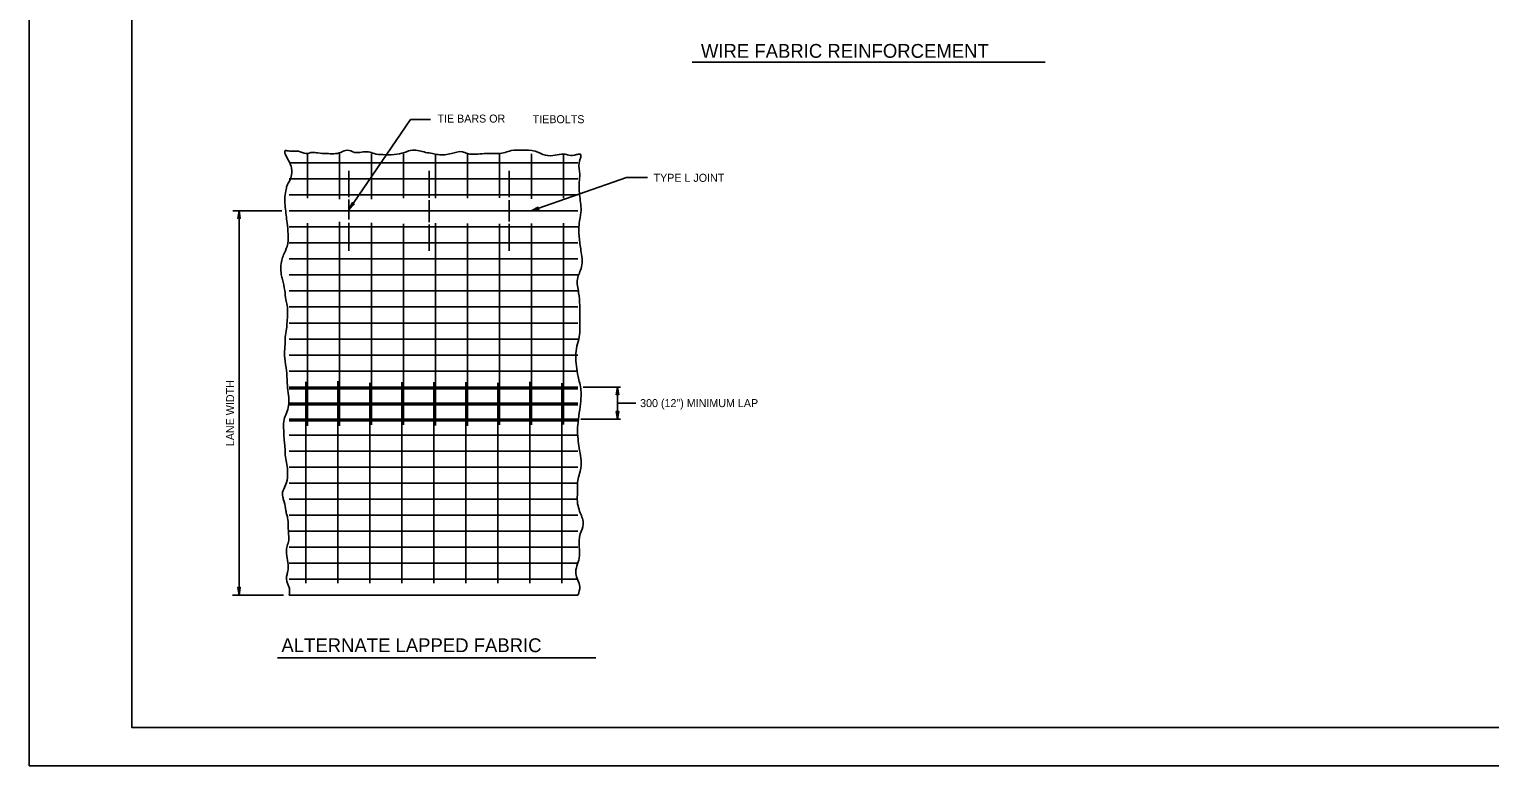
# Model space of a CAD drawing. Extents: x 638703 to 639608, y 298343 to 298937.
# Drawn here: x 638703 to 639273, y 298343 to 298630 of the extents above; entities that cross this region are included whole.
import ezdxf

# ---------------------------------------------------------------- set-up
doc = ezdxf.new("R2010")
doc.units = 0
for name, color, linetype in [('1', 7, 'Continuous'), ('2', 7, 'Continuous'), ('3', 7, 'Continuous'), ('PLT-BNDY', 7, 'Continuous')]:
    doc.layers.add(name, color=color, linetype=linetype)

msp = doc.modelspace()

# ---------------------------------------------------------------- linework, layer by layer
at = {"layer": '1'}
msp.add_lwpolyline([(639528.936, 298357.638375), (639528.936, 298921.638375), (638742.936, 298921.638375), (638742.936, 298357.638375), (639528.936, 298357.638375), (639528.936, 298383.997375), (639328.936, 298383.997375), (639328.936, 298448.674875), (639528.936, 298448.674875), (639528.936, 298477.638375), (639328.936, 298477.638375), (639328.936, 298357.638375), (639407.7375, 298357.638375), (639407.7375, 298383.997375), (639407.7375, 298357.638375), (639484.7375, 298357.638375), (639484.7375, 298383.997375), (639484.7375, 298371.680875), (639528.936, 298371.680875)], dxfattribs=at)
at = {"layer": '2'}
for p, q in [((638961.78875, 298617.283625), (639099.593, 298617.283625)), ((638851.82375, 298594.872625), (638827.7715, 298559.651875)), ((638859.66125, 298594.872625), (638851.82375, 298594.872625)), ((638917.184, 298577.958125), (638804.41525, 298577.958125)), ((638811.557, 298581.493625), (638811.557, 298564.235125)), ((638824.057, 298581.493625), (638824.057, 298563.858125)), ((638836.557, 298581.493625), (638836.557, 298563.778875)), ((638849.057, 298581.493625), (638849.057, 298564.235125)), ((638861.557, 298581.493625), (638861.557, 298564.235125)), ((638874.057, 298581.493625), (638874.057, 298564.135125)), ((638886.557, 298581.493625), (638886.557, 298564.314375)), ((638899.057, 298581.493625), (638899.057, 298563.937375)), ((638911.557, 298581.493625), (638911.557, 298564.214375)), ((638827.7715, 298574.833125), (638827.7715, 298564.543625)), ((638859.0215, 298574.833125), (638859.0215, 298564.266375)), ((638890.2715, 298574.833125), (638890.2715, 298564.543625)), ((638917.184, 298571.708125), (638804.41525, 298571.708125)), ((638936.18825, 298572.239375), (638898.934, 298559.208125)), ((638944.26325, 298572.239375), (638936.18825, 298572.239375)), ((638917.184, 298565.458125), (638804.41525, 298565.458125)), ((638827.7715, 298563.710125), (638827.7715, 298555.893625)), ((638859.0215, 298563.433125), (638859.0215, 298554.783125)), ((638890.2715, 298563.433125), (638890.2715, 298555.062375)), ((638801.53825, 298559.208125), (638782.47575, 298559.208125)), ((638784.857, 298559.208125), (638784.857, 298409.289375)), ((638917.184, 298559.208125), (638804.41525, 298559.208125)), ((638917.184, 298552.958125), (638804.41525, 298552.958125)), ((638811.557, 298554.474875), (638811.557, 298475.339375)), ((638824.057, 298554.931125), (638824.057, 298475.339375)), ((638827.7715, 298554.506125), (638827.7715, 298543.583125)), ((638836.557, 298554.574875), (638836.557, 298475.695625)), ((638849.057, 298554.118625), (638849.057, 298475.695625)), ((638859.0215, 298553.931125), (638859.0215, 298543.583125)), ((638861.557, 298554.474875), (638861.557, 298475.518625)), ((638874.057, 298554.297625), (638874.057, 298475.339375)), ((638886.557, 298554.197625), (638886.557, 298475.695625)), ((638890.2715, 298554.208125), (638890.2715, 298543.583125)), ((638899.057, 298554.297625), (638899.057, 298475.695625)), ((638911.557, 298554.376875), (638911.557, 298475.893625)), ((638917.184, 298546.708125), (638804.41525, 298546.708125)), ((638917.184, 298540.458125), (638804.41525, 298540.458125)), ((638917.184, 298534.208125), (638804.41525, 298534.208125)), ((638917.184, 298527.958125), (638804.41525, 298527.958125)), ((638917.184, 298521.708125), (638804.41525, 298521.708125)), ((638917.184, 298515.458125), (638804.41525, 298515.458125)), ((638917.184, 298509.208125), (638804.41525, 298509.208125)), ((638917.184, 298502.958125), (638804.41525, 298502.958125)), ((638917.184, 298496.708125), (638804.41525, 298496.708125)), ((638810.907, 298492.516375), (638810.907, 298413.914375)), ((638823.407, 298492.716375), (638823.407, 298413.914375)), ((638898.407, 298492.516375), (638898.407, 298413.914375)), ((638917.184, 298490.458125), (638804.41525, 298490.458125)), ((638917.184, 298489.808125), (638804.41525, 298489.808125)), ((638835.907, 298492.160125), (638835.907, 298413.914375)), ((638848.407, 298492.339375), (638848.407, 298413.914375)), ((638860.907, 298492.339375), (638860.907, 298413.914375)), ((638873.407, 298492.339375), (638873.407, 298413.914375)), ((638885.907, 298492.160125), (638885.907, 298413.914375)), ((638910.907, 298491.981125), (638910.907, 298413.914375)), ((638933.82775, 298490.458125), (638919.18825, 298490.458125)), ((638932.59875, 298490.458125), (638932.59875, 298477.958125)), ((638917.184, 298484.208125), (638804.41525, 298484.208125)), ((638917.184, 298483.558125), (638804.41525, 298483.558125)), ((638932.59875, 298484.208125), (638939.77775, 298484.208125)), ((638917.184, 298477.958125), (638804.41525, 298477.958125)), ((638917.184, 298477.308125), (638804.41525, 298477.308125)), ((638933.807, 298477.958125), (638918.2965, 298477.958125)), ((638917.184, 298471.708125), (638804.41525, 298471.708125)), ((638917.184, 298465.458125), (638804.41525, 298465.458125)), ((638917.184, 298459.208125), (638804.41525, 298459.208125)), ((638917.184, 298452.958125), (638804.41525, 298452.958125)), ((638917.184, 298446.708125), (638804.41525, 298446.708125)), ((638917.184, 298440.458125), (638804.41525, 298440.458125)), ((638917.184, 298434.208125), (638804.41525, 298434.208125)), ((638917.184, 298427.958125), (638804.41525, 298427.958125)), ((638917.184, 298421.708125), (638804.41525, 298421.708125)), ((638917.184, 298415.458125), (638804.41525, 298415.458125)), ((638802.21325, 298409.208125), (638782.23825, 298409.208125)), ((638917.184, 298409.208125), (638804.41525, 298409.208125)), ((638799.936, 298384.739375), (638924.21, 298384.739375))]:
    msp.add_line(p, q, dxfattribs=at)
for points in [[(638829.66525, 298561.795625), (638829.43625, 298561.822625), (638827.7715, 298559.651875), (638829.66525, 298561.795625), (638829.85075, 298561.843625), (638827.7715, 298559.651875), (638829.19875, 298561.983125), (638829.08825, 298562.178875), (638827.7715, 298559.651875), (638829.06325, 298562.383125), (638829.08825, 298562.178875)], [(638784.50075, 298556.451875), (638784.707, 298556.558125), (638784.857, 298559.289375), (638784.50075, 298556.451875), (638784.37575, 298556.306125), (638784.857, 298559.289375), (638784.9925, 298556.560125), (638785.1945, 298556.460125), (638784.857, 298559.289375), (638785.332, 298556.306125), (638785.1945, 298556.460125)], [(638901.73, 298559.808125), (638901.56325, 298559.968625), (638898.934, 298559.208125), (638901.73, 298559.808125), (638901.909, 298559.739375), (638898.934, 298559.208125), (638901.4675, 298560.237375), (638901.4925, 298560.462375), (638898.934, 298559.208125), (638901.5945, 298560.641375), (638901.4925, 298560.462375)], [(638932.2425, 298487.620625), (638932.44875, 298487.726875), (638932.59875, 298490.458125), (638932.2425, 298487.620625), (638932.1175, 298487.474875), (638932.59875, 298490.458125), (638932.734, 298487.728875), (638932.93625, 298487.628875), (638932.59875, 298490.458125), (638933.07375, 298487.474875), (638932.93625, 298487.628875)], [(638932.955, 298480.795625), (638932.74875, 298480.689375), (638932.59875, 298477.958125), (638932.955, 298480.795625), (638933.08, 298480.941375), (638932.59875, 298477.958125), (638932.46325, 298480.687375), (638932.26125, 298480.787375), (638932.59875, 298477.958125), (638932.12375, 298480.941375), (638932.26125, 298480.787375)], [(638785.21325, 298412.126875), (638785.007, 298412.020625), (638784.857, 298409.289375), (638785.21325, 298412.126875), (638785.33825, 298412.272625), (638784.857, 298409.289375), (638784.7215, 298412.018625), (638784.5195, 298412.118625), (638784.857, 298409.289375), (638784.382, 298412.272625), (638784.5195, 298412.118625)]]:
    msp.add_lwpolyline(points, dxfattribs=at)
for points in [[(638917.184, 298409.208125), (638917.88, 298412.537375), (638916.31125, 298417.674875), (638917.66125, 298423.706125), (638917.66125, 298427.970625), (638918.0965, 298433.108125), (638919.22775, 298436.916375), (638918.0965, 298441.378875), (638917.205, 298444.058125), (638916.98625, 298450.999875), (638916.98625, 298453.241375), (638918.33625, 298458.835125), (638917.66125, 298466.649875), (638917.205, 298470.241375), (638916.98625, 298472.701875), (638917.205, 298476.726875), (638917.88, 298481.647625), (638918.33625, 298486.110125), (638918.33625, 298489.243625), (638917.205, 298494.620625), (638916.55075, 298498.647625), (638916.7675, 298506.462375), (638917.66125, 298510.051875), (638917.88, 298516.974875), (638917.88, 298522.351875), (638917.4425, 298527.270625), (638916.98625, 298532.626875), (638918.55275, 298537.326875), (638918.33625, 298543.814375), (638917.66125, 298548.951875), (638917.66125, 298554.326875), (638918.33625, 298558.572625), (638917.88, 298564.841375), (638917.66125, 298570.435125), (638917.88, 298573.568625), (638917.66125, 298578.031125), (638918.0965, 298581.385125), (638916.55075, 298581.166375), (638913.634, 298580.947625), (638911.63, 298581.385125), (638908.259, 298580.947625), (638904.4695, 298580.947625), (638900.4425, 298582.514375), (638895.28625, 298582.951875), (638891.04025, 298582.733125), (638888.79875, 298582.058125), (638886.1215, 298581.601875), (638881.4195, 298581.601875), (638878.0675, 298581.385125), (638874.04025, 298581.601875), (638872.03825, 298582.276875), (638867.7925, 298581.601875), (638862.634, 298581.166375), (638860.41325, 298581.601875), (638857.71525, 298582.058125), (638852.57775, 298582.951875), (638849.4445, 298582.058125), (638845.4175, 298581.166375), (638840.95275, 298581.166375), (638837.60075, 298581.601875), (638835.359, 298582.276875), (638829.984, 298582.058125), (638827.08825, 298582.951875), (638824.62775, 298582.058125), (638819.034, 298581.601875), (638815.682, 298581.841375), (638813.44025, 298582.058125), (638810.982, 298581.601875), (638808.06525, 298582.514375), (638804.71325, 298582.514375), (638802.92775, 298582.733125), (638804.27575, 298578.706125), (638805.1695, 298576.683125), (638805.38825, 298573.331125), (638804.4945, 298570.870625), (638803.60275, 298569.085125), (638803.1465, 298567.083125), (638802.709, 298563.947625), (638802.92775, 298560.595625), (638803.60275, 298554.545625), (638804.03825, 298550.083125), (638803.60275, 298545.381125), (638802.25275, 298542.028875), (638801.57775, 298540.006125), (638801.36125, 298534.431125), (638801.8175, 298532.408125), (638802.709, 298528.162375), (638803.1465, 298524.572625), (638803.60275, 298522.351875), (638803.60275, 298515.864375), (638803.384, 298513.166375), (638802.92775, 298509.814375), (638802.92775, 298508.922625), (638802.709, 298505.351875), (638802.709, 298501.760125), (638803.384, 298496.841375), (638803.60275, 298493.708125)], [(638803.60275, 298493.708125), (638803.8195, 298490.137375), (638804.27575, 298486.328875), (638803.384, 298480.297625), (638802.4715, 298477.839375), (638802.25275, 298474.485125), (638802.4715, 298470.241375), (638802.709, 298467.781125), (638802.92775, 298464.866375), (638802.92775, 298463.972625), (638803.8195, 298457.943625), (638803.8195, 298456.812375), (638803.384, 298453.241375), (638801.8175, 298448.083125), (638802.034, 298447.191375), (638802.4715, 298445.624875), (638803.1465, 298442.272625), (638803.384, 298440.943625), (638803.8195, 298439.374875), (638804.03825, 298436.460125), (638804.27575, 298431.995625), (638804.27575, 298430.647625), (638803.60275, 298428.406125), (638803.384, 298427.295625), (638803.60275, 298423.706125), (638804.03825, 298420.351875), (638803.8195, 298418.131125), (638803.384, 298416.564375), (638804.27575, 298412.537375), (638804.4945, 298411.862375), (638804.41525, 298409.208125)]]:
    msp.add_spline(points, degree=3, dxfattribs=at)
at = {"layer": 'PLT-BNDY'}
msp.add_lwpolyline([(638702.936, 298936.638375), (639543.936, 298936.638375), (639543.936, 298342.638375), (638702.936, 298342.638375)], close=True, dxfattribs=at)

# ---------------------------------------------------------------- texts
at = {"layer": '3'}
for s, height, p in [('WIRE FABRIC REINFORCEMENT', 5.4020865, (638965.1805, 298618.962875)), ('TIE BARS OR', 3.1249995, (638862.3195, 298593.681125)), ('TIEBOLTS', 3.1249995, (638899.4925, 298593.445625)), ('TYPE L JOINT', 3.1249995, (638946.684, 298570.574875)), ('300 (12") MINIMUM LAP', 3.1249995, (638941.4445, 298482.637375)), ('ALTERNATE LAPPED FABRIC', 5.4020865, (638801.3945, 298386.985125))]:
    msp.add_text(s, height=height, dxfattribs=at).set_placement(p)
msp.add_text('LANE WIDTH', height=3.1249995, rotation=90, dxfattribs=at).set_placement((638782.95275, 298467.385125))

doc.saveas('drawing.dxf')
